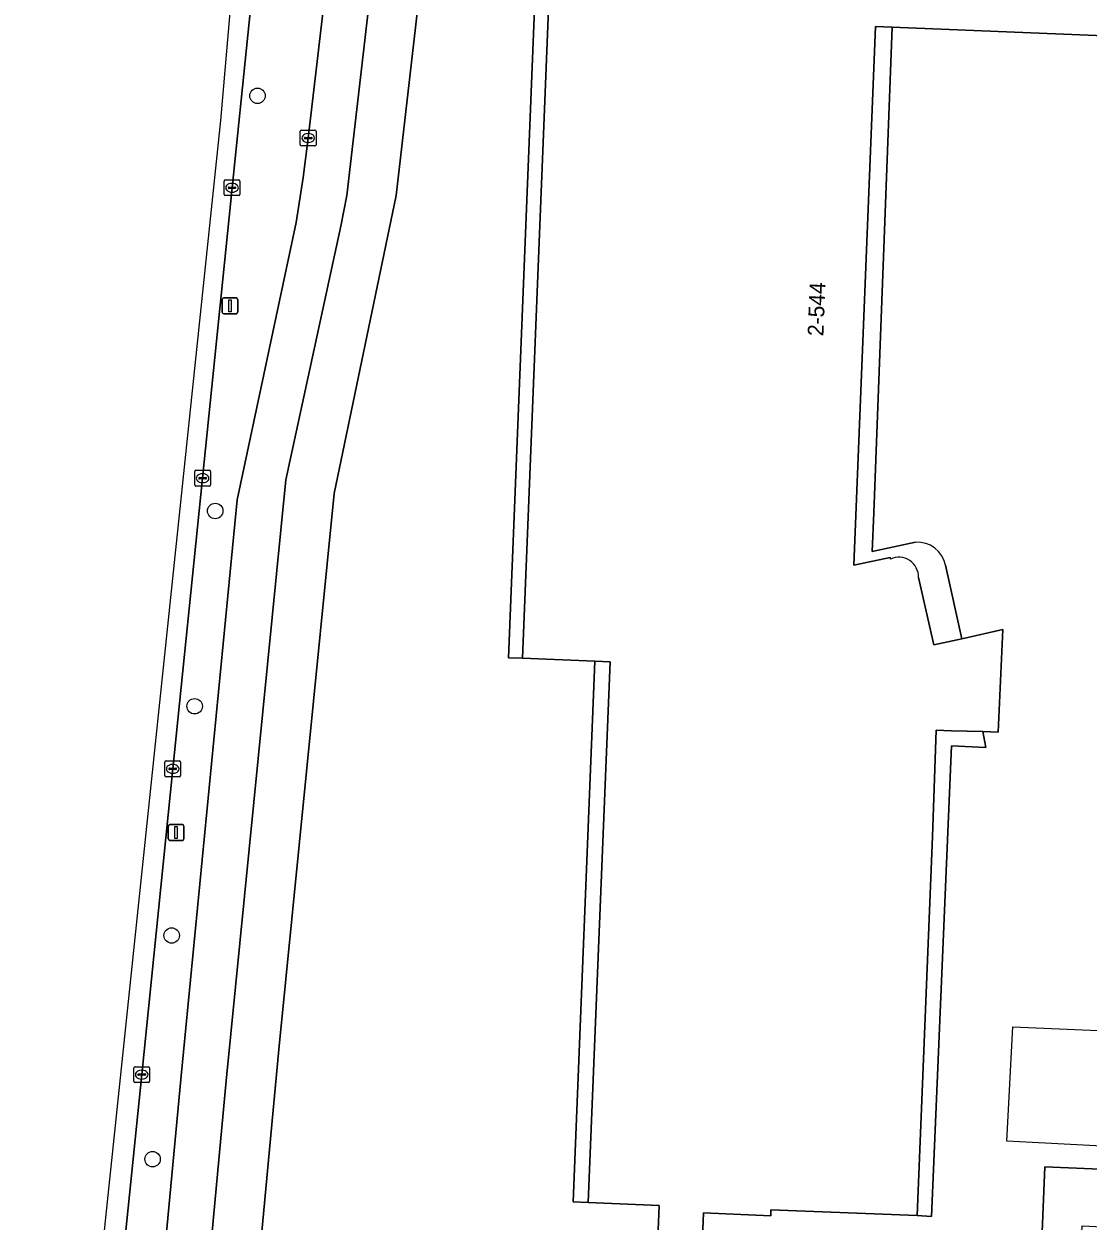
# Model space of a CAD drawing. Extents: x 161354 to 162026, y 386504 to 387460.
# Drawn here: x 161355.5 to 161423, y 386577.7 to 386653.6 of the extents above; entities that cross this region are included whole.
import ezdxf

# ---------------------------------------------------------------- set-up
doc = ezdxf.new("R2010")
doc.units = 0
for name, color, linetype in [('IMGEO_Berm_groen', 7, 'Continuous'), ('IMGEO_Boom', 7, 'Continuous'), ('IMGEO_Erf', 7, 'Continuous'), ('IMGEO_Fietspad_open', 7, 'Continuous'), ('IMGEO_Kolk', 7, 'Continuous'), ('IMGEO_Lichtmast', 7, 'Continuous'), ('IMGEO_Pand', 7, 'Continuous'), ('IMGEO_Pand_nummerreeks', 7, 'Continuous'), ('IMGEO_Pand_vergunning_verleend', 7, 'Continuous'), ('IMGEO_Rijbaan_lokaal_gesloten', 7, 'Continuous'), ('IMGEO_Voetpad_open', 7, 'Continuous')]:
    doc.layers.add(name, color=color, linetype=linetype)

msp = doc.modelspace()

# ---------------------------------------------------------------- linework, layer by layer
at = {"layer": 'IMGEO_Berm_groen'}
for points in [[(161376.396, 386717.844), (161375.309, 386707.309), (161373.851, 386693.007), (161372.926, 386683.94), (161370.724, 386662.56), (161368.724, 386643.195), (161366.857, 386624.793), (161364.968, 386606.376), (161363.004, 386587.003), (161361.03, 386567.642), (161359.038, 386548.229), (161357.055, 386528.822), (161356.983, 386528.182), (161356.845, 386526.767)], [(161369.056, 386623.43), (161372.78, 386641.005), (161373.235, 386643.851), (161373.548, 386646.346), (161375.763, 386665.263), (161375.91, 386666.917), (161376.529, 386689.717), (161378.997, 386712.85), (161379.452, 386716.1)], [(161361.751, 386546.816), (161365.503, 386586.919), (161369.056, 386623.43)]]:
    msp.add_lwpolyline(points, dxfattribs=at)
at = {"layer": 'IMGEO_Boom'}
for centre in [(161370.335, 386649.024), (161367.658, 386622.716), (161366.353, 386610.342), (161364.898, 386595.817), (161363.689, 386581.642)]:
    msp.add_circle(centre, 0.489, dxfattribs=at)
at = {"layer": 'IMGEO_Erf'}
for points in [[(161414.901, 386701.354), (161414.917, 386701.76), (161419.974, 386701.557), (161419.96, 386701.211), (161426.445, 386700.95), (161427.367, 386700.915), (161425.432, 386652.773), (161424.51, 386652.81), (161410.533, 386653.372), (161409.388, 386622.596), (161409.271, 386620.154), (161412.023, 386620.738)], [(161381.851, 386666.399), (161379.125, 386642.696), (161375.198, 386623.821), (161371.689, 386588.597), (161367.56, 386544.47)], [(161395.387, 386568.79), (161395.786, 386578.714), (161391.29, 386578.895), (161390.331, 386578.937), (161391.709, 386613.201), (161387.123, 386613.385), (161386.228, 386613.419), (161388.149, 386661.399)], [(161413.919, 386619.291), (161414.949, 386614.624), (161417.546, 386615.212), (161417.26, 386608.709), (161416.279, 386608.742), (161416.467, 386607.728), (161414.293, 386607.834), (161413.038, 386578.017), (161412.137, 386578.072), (161402.865, 386578.43), (161402.85, 386578.064), (161398.585, 386578.236), (161398.193, 386568.482)], [(161418.55, 386540.528), (161420.217, 386581.152), (161436.711, 386580.469)]]:
    msp.add_lwpolyline(points, dxfattribs=at)
msp.add_arc((161412.14, 386618.925), 1.817, 11.62052, 93.67878, dxfattribs=at)
at = {"layer": 'IMGEO_Fietspad_open'}
for points in [[(161368.347, 386586.608), (161372.137, 386624.68), (161375.624, 386640.752), (161375.998, 386642.707), (161378.77, 386666.617), (161379.47, 386690.727), (161381.864, 386712.557), (161378.997, 386712.85), (161376.529, 386689.717), (161375.91, 386666.917), (161375.763, 386665.263), (161373.548, 386646.346), (161373.235, 386643.851), (161372.78, 386641.005), (161369.056, 386623.43), (161365.503, 386586.919), (161361.751, 386546.816)], [(161361.437, 386536.487), (161361.45, 386533.416), (161364.391, 386533.313), (161364.37, 386537.917), (161364.326, 386538.115), (161364.3, 386538.317), (161364.292, 386538.52), (161364.303, 386538.723), (161364.392, 386543.778), (161364.46, 386544.778), (161368.347, 386586.608)]]:
    msp.add_lwpolyline(points, dxfattribs=at)
at = {"layer": 'IMGEO_Kolk'}
for p, q in [((161373.047, 386645.92), (161373.047, 386646.772)), ((161373.122, 386646.846), (161373.974, 386646.846)), ((161373.306, 386646.34), (161373.306, 386646.352)), ((161373.744, 386646.303), (161373.346, 386646.303)), ((161373.349, 386646.389), (161373.747, 386646.389)), ((161373.535, 386646.626), (161373.56, 386646.626)), ((161373.79, 386646.352), (161373.79, 386646.34)), ((161374.048, 386646.772), (161374.048, 386645.92)), ((161373.974, 386645.846), (161373.122, 386645.846)), ((161373.558, 386646.066), (161373.533, 386646.066)), ((161368.223, 386642.769), (161368.223, 386643.621)), ((161368.298, 386643.695), (161369.15, 386643.695)), ((161368.525, 386643.238), (161368.923, 386643.238)), ((161368.711, 386643.475), (161368.736, 386643.475)), ((161369.224, 386643.621), (161369.224, 386642.769)), ((161369.15, 386642.695), (161368.298, 386642.695)), ((161368.482, 386643.189), (161368.482, 386643.201)), ((161368.92, 386643.152), (161368.522, 386643.152)), ((161368.734, 386642.915), (161368.709, 386642.915)), ((161368.966, 386643.201), (161368.966, 386643.189)), ((161366.356, 386624.367), (161366.356, 386625.219)), ((161366.431, 386625.293), (161367.283, 386625.293)), ((161366.844, 386625.073), (161366.869, 386625.073)), ((161367.357, 386625.219), (161367.357, 386624.367)), ((161367.283, 386624.293), (161366.431, 386624.293)), ((161366.615, 386624.787), (161366.615, 386624.799)), ((161367.053, 386624.75), (161366.655, 386624.75)), ((161366.658, 386624.836), (161367.056, 386624.836)), ((161366.867, 386624.513), (161366.842, 386624.513)), ((161367.099, 386624.799), (161367.099, 386624.787)), ((161364.542, 386606.876), (161365.394, 386606.876)), ((161364.467, 386605.95), (161364.467, 386606.802)), ((161364.726, 386606.37), (161364.726, 386606.382)), ((161365.164, 386606.333), (161364.766, 386606.333)), ((161364.769, 386606.419), (161365.167, 386606.419)), ((161364.978, 386606.096), (161364.953, 386606.096)), ((161364.955, 386606.656), (161364.98, 386606.656)), ((161365.21, 386606.382), (161365.21, 386606.37)), ((161365.468, 386606.802), (161365.468, 386605.95)), ((161365.394, 386605.876), (161364.542, 386605.876)), ((161362.503, 386586.577), (161362.503, 386587.429)), ((161362.578, 386587.503), (161363.43, 386587.503)), ((161362.991, 386587.283), (161363.016, 386587.283)), ((161363.504, 386587.429), (161363.504, 386586.577)), ((161363.43, 386586.503), (161362.578, 386586.503)), ((161362.762, 386586.997), (161362.762, 386587.009)), ((161363.2, 386586.96), (161362.802, 386586.96)), ((161362.805, 386587.046), (161363.203, 386587.046)), ((161363.014, 386586.723), (161362.989, 386586.723)), ((161363.246, 386587.009), (161363.246, 386586.997))]:
    msp.add_line(p, q, dxfattribs=at)
for points in [[(161373.047, 386645.92), (161373.047, 386646.772)], [(161373.122, 386646.846), (161373.974, 386646.846)], [(161374.048, 386646.772), (161374.048, 386645.92)], [(161373.974, 386645.846), (161373.122, 386645.846)], [(161368.223, 386642.769), (161368.223, 386643.621)], [(161368.298, 386643.695), (161369.15, 386643.695)], [(161369.224, 386643.621), (161369.224, 386642.769)], [(161369.15, 386642.695), (161368.298, 386642.695)], [(161366.356, 386624.367), (161366.356, 386625.219)], [(161366.431, 386625.293), (161367.283, 386625.293)], [(161367.357, 386625.219), (161367.357, 386624.367)], [(161367.283, 386624.293), (161366.431, 386624.293)], [(161364.542, 386606.876), (161365.394, 386606.876)], [(161364.467, 386605.95), (161364.467, 386606.802)], [(161365.468, 386606.802), (161365.468, 386605.95)], [(161365.394, 386605.876), (161364.542, 386605.876)], [(161362.503, 386586.577), (161362.503, 386587.429)], [(161362.578, 386587.503), (161363.43, 386587.503)], [(161363.504, 386587.429), (161363.504, 386586.577)], [(161363.43, 386586.503), (161362.578, 386586.503)]]:
    msp.add_lwpolyline(points, dxfattribs=at)
for centre, radius, start, end in [((161373.124, 386646.77), 0.0765, 91.55205, 178.44795), ((161373.124, 386646.77), 0.0765, 91.55205, 178.44795), ((161373.346, 386646.349), 0.0403, 85.87752, 175.75265), ((161373.343, 386646.339), 0.0366, 178.93798, 274.71019), ((161373.747, 386646.346), 0.043, 264.86636, 352.45326), ((161373.751, 386646.351), 0.0386, 1.73085, 96.63898), ((161373.972, 386646.77), 0.0765, 1.55205, 88.44795), ((161373.972, 386646.77), 0.0765, 1.55205, 88.44795), ((161373.124, 386645.922), 0.0765, 181.55205, 268.44795), ((161373.124, 386645.922), 0.0765, 181.55205, 268.44795), ((161373.972, 386645.922), 0.0765, 271.55205, 358.44795), ((161373.972, 386645.922), 0.0765, 271.55205, 358.44795), ((161368.3, 386643.619), 0.0765, 91.55205, 178.44795), ((161368.3, 386643.619), 0.0765, 91.55205, 178.44795), ((161368.522, 386643.198), 0.0403, 85.87752, 175.75265), ((161368.927, 386643.2), 0.0386, 1.73085, 96.63898), ((161369.148, 386643.619), 0.0765, 1.55205, 88.44795), ((161369.148, 386643.619), 0.0765, 1.55205, 88.44795), ((161368.3, 386642.771), 0.0765, 181.55205, 268.44795), ((161368.3, 386642.771), 0.0765, 181.55205, 268.44795), ((161368.519, 386643.188), 0.0366, 178.93798, 274.71019), ((161368.923, 386643.195), 0.043, 264.86636, 352.45326), ((161369.148, 386642.771), 0.0765, 271.55205, 358.44795), ((161369.148, 386642.771), 0.0765, 271.55205, 358.44795), ((161366.433, 386625.217), 0.0765, 91.55205, 178.44795), ((161366.433, 386625.217), 0.0765, 91.55205, 178.44795), ((161367.281, 386625.217), 0.0765, 1.55205, 88.44795), ((161367.281, 386625.217), 0.0765, 1.55205, 88.44795), ((161366.433, 386624.369), 0.0765, 181.55205, 268.44795), ((161366.433, 386624.369), 0.0765, 181.55205, 268.44795), ((161366.655, 386624.796), 0.0403, 85.87752, 175.75265), ((161366.652, 386624.786), 0.0366, 178.93798, 274.71019), ((161367.056, 386624.793), 0.043, 264.86636, 352.45326), ((161367.06, 386624.798), 0.0386, 1.73085, 96.63898), ((161367.281, 386624.369), 0.0765, 271.55205, 358.44795), ((161367.281, 386624.369), 0.0765, 271.55205, 358.44795), ((161364.544, 386606.8), 0.0765, 91.55205, 178.44795), ((161364.544, 386606.8), 0.0765, 91.55205, 178.44795), ((161365.392, 386606.8), 0.0765, 1.55205, 88.44795), ((161365.392, 386606.8), 0.0765, 1.55205, 88.44795), ((161364.766, 386606.379), 0.0403, 85.87752, 175.75265), ((161364.763, 386606.369), 0.0366, 178.93798, 274.71019), ((161365.167, 386606.376), 0.043, 264.86636, 352.45326), ((161365.171, 386606.381), 0.0386, 1.73085, 96.63898), ((161364.544, 386605.952), 0.0765, 181.55205, 268.44795), ((161364.544, 386605.952), 0.0765, 181.55205, 268.44795), ((161365.392, 386605.952), 0.0765, 271.55205, 358.44795), ((161365.392, 386605.952), 0.0765, 271.55205, 358.44795), ((161362.58, 386587.427), 0.0765, 91.55205, 178.44795), ((161362.58, 386587.427), 0.0765, 91.55205, 178.44795), ((161363.428, 386587.427), 0.0765, 1.55205, 88.44795), ((161363.428, 386587.427), 0.0765, 1.55205, 88.44795), ((161362.58, 386586.579), 0.0765, 181.55205, 268.44795), ((161362.58, 386586.579), 0.0765, 181.55205, 268.44795), ((161362.802, 386587.006), 0.0403, 85.87752, 175.75265), ((161362.799, 386586.996), 0.0366, 178.93798, 274.71019), ((161363.203, 386587.003), 0.043, 264.86636, 352.45326), ((161363.207, 386587.008), 0.0386, 1.73085, 96.63898), ((161363.428, 386586.579), 0.0765, 271.55205, 358.44795), ((161363.428, 386586.579), 0.0765, 271.55205, 358.44795)]:
    msp.add_arc(centre, radius, start, end, dxfattribs=at)
for centre, major_axis, ratio, start_param, end_param in [((161373.534, 386646.346), (-0.387, 0.002), 0.722429, 4.712389, 7.853982), ((161373.559, 386646.346), (-0.39, 0.002), 0.717154, 1.570796, 4.712389), ((161368.71, 386643.195), (-0.387, 0.002), 0.722429, 4.712389, 7.853982), ((161368.735, 386643.195), (-0.39, 0.002), 0.717154, 1.570796, 4.712389), ((161366.843, 386624.793), (-0.387, 0.002), 0.722429, 4.712389, 7.853982), ((161366.868, 386624.793), (-0.39, 0.002), 0.717154, 1.570796, 4.712389), ((161364.954, 386606.376), (-0.387, 0.002), 0.722429, 4.712389, 7.853982), ((161364.979, 386606.376), (-0.39, 0.002), 0.717154, 1.570796, 4.712389), ((161362.99, 386587.003), (-0.387, 0.002), 0.722429, 4.712389, 7.853982), ((161363.015, 386587.003), (-0.39, 0.002), 0.717154, 1.570796, 4.712389)]:
    msp.add_ellipse(centre, major_axis=major_axis, ratio=ratio, start_param=start_param, end_param=end_param, dxfattribs=at)
at = {"layer": 'IMGEO_Lichtmast'}
for p, q in [((161368.094, 386635.311), (161368.094, 386636.111)), ((161368.094, 386636.111), (161368.094, 386635.311)), ((161368.194, 386636.211), (161368.984, 386636.211)), ((161368.984, 386636.211), (161368.194, 386636.211)), ((161369.084, 386636.111), (161369.084, 386635.311)), ((161369.084, 386635.311), (161369.084, 386636.111)), ((161368.984, 386635.211), (161368.194, 386635.211)), ((161368.194, 386635.211), (161368.984, 386635.211)), ((161364.687, 386601.943), (161364.687, 386602.743)), ((161364.687, 386602.743), (161364.687, 386601.943)), ((161364.787, 386602.843), (161365.577, 386602.843)), ((161365.577, 386602.843), (161364.787, 386602.843)), ((161365.677, 386602.743), (161365.677, 386601.943)), ((161365.677, 386601.943), (161365.677, 386602.743)), ((161365.577, 386601.843), (161364.787, 386601.843)), ((161364.787, 386601.843), (161365.577, 386601.843))]:
    msp.add_line(p, q, dxfattribs=at)
for points in [[(161368.514, 386636.086), (161368.664, 386636.086), (161368.664, 386635.336), (161368.514, 386635.336), (161368.514, 386636.086)], [(161365.107, 386602.718), (161365.257, 386602.718), (161365.257, 386601.968), (161365.107, 386601.968), (161365.107, 386602.718)]]:
    msp.add_lwpolyline(points, dxfattribs=at)
for centre, start, end in [((161368.194, 386636.111), 90, 180), ((161368.194, 386636.111), 90, 180), ((161368.984, 386636.111), 0, 90), ((161368.984, 386636.111), 360, 90), ((161368.194, 386635.311), 180, 270), ((161368.194, 386635.311), 180, 270), ((161368.984, 386635.311), 270, 0), ((161368.984, 386635.311), 270, 0), ((161364.787, 386602.743), 90, 180), ((161364.787, 386602.743), 90, 180), ((161365.577, 386602.743), 0, 90), ((161365.577, 386602.743), 360, 90), ((161364.787, 386601.943), 180, 270), ((161364.787, 386601.943), 180, 270), ((161365.577, 386601.943), 270, 0), ((161365.577, 386601.943), 270, 0)]:
    msp.add_arc(centre, 0.1, start, end, dxfattribs=at)
at = {"layer": 'IMGEO_Pand'}
for points in [[(161409.496, 386653.414), (161410.533, 386653.372), (161424.51, 386652.81), (161426.445, 386700.95)], [(161389.052, 386661.366), (161387.123, 386613.385), (161391.709, 386613.201), (161392.668, 386613.162), (161391.29, 386578.895), (161395.786, 386578.714), (161395.387, 386568.79)], [(161410.439, 386619.665), (161410.406, 386619.764), (161408.124, 386619.286), (161409.496, 386653.414)], [(161398.193, 386568.482), (161398.585, 386578.236), (161402.85, 386578.064), (161402.865, 386578.43), (161412.137, 386578.072), (161413.089, 386602.081), (161413.34, 386608.823), (161414.309, 386608.787), (161416.279, 386608.742), (161417.26, 386608.709), (161417.546, 386615.212), (161414.949, 386614.624), (161413.178, 386614.235), (161412.209, 386618.494)]]:
    msp.add_lwpolyline(points, dxfattribs=at)
msp.add_arc((161410.97, 386618.545), 1.24, 357.65154, 115.37266, dxfattribs=at)
at = {"layer": 'IMGEO_Pand_vergunning_verleend'}
msp.add_lwpolyline([(161417.808, 386582.78), (161418.178, 386590.027), (161434.891, 386589.315), (161434.754, 386581.904)], close=True, dxfattribs=at)
at = {"layer": 'IMGEO_Rijbaan_lokaal_gesloten'}
msp.add_lwpolyline([(161355.54, 386522.826), (161357.351, 386522.917), (161356.857, 386525.302), (161356.845, 386526.767), (161356.983, 386528.182), (161357.055, 386528.822), (161359.038, 386548.229), (161361.03, 386567.642), (161363.004, 386587.003), (161364.968, 386606.376), (161366.857, 386624.793), (161368.724, 386643.195), (161370.724, 386662.56), (161372.926, 386683.94), (161373.851, 386693.007), (161371.943, 386693.186), (161367.997, 386647.461), (161359.985, 386571.09), (161356.711, 386535.543)], close=True, dxfattribs=at)
at = {"layer": 'IMGEO_Voetpad_open'}
for points in [[(161378.77, 386666.617), (161375.998, 386642.707), (161375.624, 386640.752), (161372.137, 386624.68), (161368.347, 386586.608), (161364.46, 386544.778)], [(161367.56, 386544.47), (161371.689, 386588.597), (161375.198, 386623.821), (161379.125, 386642.696), (161381.851, 386666.399)], [(161412.023, 386620.738), (161409.271, 386620.154), (161409.388, 386622.596), (161410.533, 386653.372), (161409.496, 386653.414), (161408.124, 386619.286), (161410.406, 386619.764), (161410.439, 386619.665)], [(161412.209, 386618.494), (161413.178, 386614.235), (161414.949, 386614.624), (161413.919, 386619.291)], [(161440.612, 386579.503), (161436.711, 386580.469), (161420.217, 386581.152), (161418.55, 386540.528), (161418.541, 386540.389), (161418.612, 386534.37), (161418.897, 386534.449), (161419.174, 386534.553), (161419.44, 386534.682), (161419.694, 386534.833), (161419.934, 386535.007), (161420.156, 386535.202), (161420.361, 386535.415), (161420.546, 386535.647), (161420.709, 386535.893), (161420.849, 386536.153), (161420.966, 386536.425), (161421.058, 386536.706), (161421.125, 386536.994), (161421.165, 386537.287), (161421.177, 386537.467), (161422.296, 386571.701), (161422.578, 386577.43), (161437.448, 386576.695)]]:
    msp.add_lwpolyline(points, dxfattribs=at)
for points in [[(161389.052, 386661.366), (161388.149, 386661.399), (161386.228, 386613.419), (161387.123, 386613.385)], [(161392.668, 386613.162), (161391.709, 386613.201), (161390.331, 386578.937), (161391.29, 386578.895)], [(161414.309, 386608.787), (161413.34, 386608.823), (161413.089, 386602.081), (161412.137, 386578.072), (161413.038, 386578.017), (161414.293, 386607.834), (161416.467, 386607.728), (161416.279, 386608.742)]]:
    msp.add_lwpolyline(points, close=True, dxfattribs=at)
for centre, radius, start, end in [((161412.14, 386618.925), 1.817, 11.62052, 93.67878), ((161410.97, 386618.545), 1.24, 357.65154, 115.37266)]:
    msp.add_arc(centre, radius, start, end, dxfattribs=at)

# ---------------------------------------------------------------- texts
at = {"layer": 'IMGEO_Pand_nummerreeks'}
msp.add_text('2-544', height=1, rotation=87.69692, dxfattribs=at).set_placement((161406.184, 386633.776))

doc.saveas('drawing.dxf')
